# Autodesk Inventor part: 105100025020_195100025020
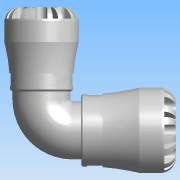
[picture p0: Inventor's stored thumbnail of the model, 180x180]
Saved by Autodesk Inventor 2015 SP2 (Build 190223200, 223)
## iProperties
Created: 2016-12
Part Number: 105100025020_195100025020
Material: PVC-Piping
Description: PLASSON 90° REDUCING ELBOW 25-20 SERIES 1
Document SubType Name: Modeling
Designer: KIM
Mass: 664.223 g
Surface Area: 733.008 cm^2
Volume: 474.445 cm^3
Density: 1.4 g/cm^3
Appearance: Smooth - White
Author: KIM
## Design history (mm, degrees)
derived "1051.ipt"
feature "Solid1::1051.ipt"
tag "TaggingFeature1"
body "Solid1"
other parameters: "d9" = 7.875, "d11" = 47, "d12" = 31.25, "d230" = 41, "d231" = 25, "d232" = 8, "d1" = 20.16, "d2" = 25, "d3" = 31.25, "d4" = 47, "d8" = 39.95, "d13" = 6.3, "d14" = 6.3, "d15" = 0, "d17" = 360 deg, "d19" = 8 deg, "d20" = 0.5, "d21" = 0.5, "d22" = 8 deg, "d24" = 0, "d26" = 360 deg, "d33" = 4.7, "d51" = 0.47, "d54" = 8.75, "d55" = 5.5, "d57" = 12.348, "d58" = 0, "d74" = 0, "d77" = 2.08333, "d78" = 48, "d82" = 0.5, "d115" = 360 deg, "d207" = 90 deg, "d209" = 19.32, "d211" = 25, "d212" = 41, "d213" = 34.85, "d216" = 1.66667, "d217" = 46, "d226" = 46, "d228" = 7.4375, "d229" = 6.4, "d233" = 6.4, "d234" = 0, "d236" = 360 deg, "d238" = 8 deg, "d239" = 8 deg, "d240" = 0.5, "d241" = 0.5, "d243" = 0, "d245" = 360 deg, "d247" = 0.94, "d248" = 2.88, "d249" = 2.76, "d250" = 5.95, "d252" = 7, "d253" = 4.6, "d254" = 12.348, "d255" = 0, "d257" = 360 deg, "d259" = 0.5, "d261" = 0, "d262" = 0.94, "d268" = 68, "d269" = 0, "d270" = 2.76, "d271" = 74, "d272" = 36.66, "d273" = 21.9725, "d274" = 31.98, "d275" = 0, "d276" = 0, "d_" = 25, "E_" = 47, "l_" = 48, "A_1" = 68, "A_" = 74, "E_1" = 41, "l_1" = 46
